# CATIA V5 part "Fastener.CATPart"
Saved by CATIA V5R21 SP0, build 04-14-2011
Part number: Fastener
Bounding box of the stored display mesh (mm): x -4.826 to 4.826, y -4.826 to 4.826, z -47.752 to 0
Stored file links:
  D:\CATIA V5R21 E-RESOURCES\CATIA-V5R21\catia-v5r21-Prts\c13_catia_v5r21_prt\c13_catia_v5r21_figr_13-43\Part & Asm files\Fastener.CATPart
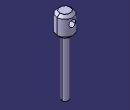
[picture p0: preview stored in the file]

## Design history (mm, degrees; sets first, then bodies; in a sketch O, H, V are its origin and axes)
Body1 (main body)
  Sketch1 on xy-plane, origin (0, 0, 0), H (1, 0, 0), V (0, 1, 0)
    circle A1 centre (0, 0) radius 4.826
    circle A2 centre (0, 0) radius 1.905
    radius A2 = 1.905
    radius A1 = 4.826
  MultiPad1: profile Sketch1, domains (length 0 / length 47.752; length 0 / length 12.7)
  Chamfer1: length 1.5875, angle 45, on 2 edges
  Chamfer2: length 0.508, angle 45, on 1 edge
  Sketch2 on zx-plane, origin (-1.612, 0, 1.612), H (1, 0, 0), V (0, 0, -1)
    point P1 (1.612, 6.35)
    reference intersected line E1 through (1.612, 0) direction (0, 1) from yz-plane
    distance P1 H = 6.35
    coincidence: E1 P1
  Hole1: placed by Sketch2, at (0, 0, -4.738) direction (0, -1, 0), diameter 4.064, depth 10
